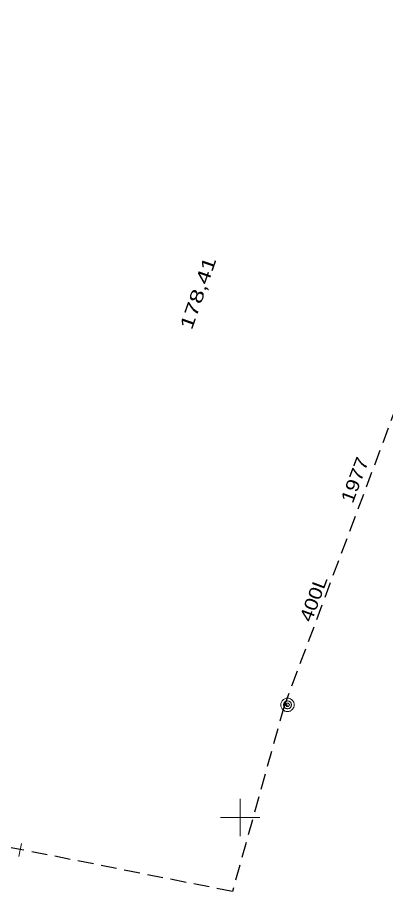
# Model space of a CAD drawing. Extents: x -740851 to -738888, y -1041382 to -1040235.
# Drawn here: x -740667 to -740638.9, y -1040305.7 to -1040239 of the extents above; entities that cross this region are included whole.
import ezdxf

# ---------------------------------------------------------------- set-up
doc = ezdxf.new("R2010")
doc.units = 0
doc.header["$LTSCALE"] = 0.4
doc.linetypes.add('MEDIUM_DASHED', pattern=[4.5, 3, -1.5])
for name, color, linetype, lineweight in [('1', 7, 'Continuous', 13), ('18', 7, 'Continuous', 13), ('8', 7, 'Continuous', 13)]:
    doc.layers.add(name, color=color, linetype=linetype, lineweight=lineweight)

msp = doc.modelspace()

# ---------------------------------------------------------------- linework, layer by layer
at = {"layer": '1'}
for p, q in [((-740650, -1040298.571), (-740650, -1040301.429)), ((-740651.48, -1040300), (-740648.48, -1040300))]:
    msp.add_line(p, q, dxfattribs=at)
at = {"layer": '8'}
for p, q in [((-740646.639, -1040291.414), (-740646.539, -1040291.314)), ((-740646.639, -1040291.314), (-740646.539, -1040291.414)), ((-740646.639, -1040291.314), (-740646.639, -1040291.334)), ((-740646.639, -1040291.314), (-740646.619, -1040291.314)), ((-740646.539, -1040291.314), (-740646.559, -1040291.314)), ((-740646.539, -1040291.314), (-740646.539, -1040291.334)), ((-740646.639, -1040291.414), (-740646.639, -1040291.394)), ((-740646.639, -1040291.414), (-740646.619, -1040291.414)), ((-740646.539, -1040291.414), (-740646.559, -1040291.414)), ((-740646.539, -1040291.414), (-740646.539, -1040291.394)), ((-740666.867, -1040302.98), (-740666.669, -1040301.98))]:
    msp.add_line(p, q, dxfattribs=at)
at = {"layer": '8', "lineweight": 25}
for p, q in [((-740646.59, -1040291.365), (-740646.39, -1040291.44)), ((-740666.76, -1040302.44), (-740667.435, -1040302.329))]:
    msp.add_line(p, q, dxfattribs=at)
at = {"layer": '8', "linetype": 'MEDIUM_DASHED', "lineweight": 25}
for points in [[(-740620.084, -1040238.965), (-740638.07, -1040268.62), (-740646.59, -1040291.365)], [(-740646.59, -1040291.365), (-740646.64, -1040291.5), (-740650.58, -1040305.65), (-740666.76, -1040302.44)]]:
    msp.add_lwpolyline(points, dxfattribs=at)
at = {"layer": '8'}
for points in [[(-740645.875, -1040291.409), (-740645.875, -1040291.364), (-740645.875, -1040291.303), (-740645.89, -1040291.258), (-740645.905, -1040291.197), (-740645.935, -1040291.152), (-740645.965, -1040291.106), (-740645.996, -1040291.076), (-740646.041, -1040291.031), (-740646.072, -1040291), (-740646.117, -1040290.97), (-740646.162, -1040290.94), (-740646.223, -1040290.924), (-740646.268, -1040290.909), (-740646.329, -1040290.909), (-740646.375, -1040290.909), (-740646.435, -1040290.909), (-740646.481, -1040290.909), (-740646.526, -1040290.924), (-740646.587, -1040290.94), (-740646.632, -1040290.97), (-740646.678, -1040291), (-740646.708, -1040291.031), (-740646.753, -1040291.076), (-740646.784, -1040291.106), (-740646.814, -1040291.152), (-740646.844, -1040291.197), (-740646.859, -1040291.258), (-740646.875, -1040291.303), (-740646.875, -1040291.364), (-740646.875, -1040291.409), (-740646.875, -1040291.47), (-740646.875, -1040291.515), (-740646.859, -1040291.561), (-740646.844, -1040291.621), (-740646.814, -1040291.667), (-740646.784, -1040291.712), (-740646.753, -1040291.743), (-740646.708, -1040291.788), (-740646.678, -1040291.818), (-740646.632, -1040291.849), (-740646.587, -1040291.879), (-740646.526, -1040291.894), (-740646.481, -1040291.909), (-740646.435, -1040291.909), (-740646.375, -1040291.909), (-740646.329, -1040291.909), (-740646.268, -1040291.909), (-740646.223, -1040291.894), (-740646.162, -1040291.879), (-740646.117, -1040291.849), (-740646.072, -1040291.818), (-740646.041, -1040291.788), (-740645.996, -1040291.743), (-740645.965, -1040291.712), (-740645.935, -1040291.667), (-740645.905, -1040291.621), (-740645.89, -1040291.561), (-740645.875, -1040291.515), (-740645.875, -1040291.47)], [(-740646.072, -1040291.409), (-740646.072, -1040291.379), (-740646.087, -1040291.349), (-740646.087, -1040291.318), (-740646.102, -1040291.288), (-740646.117, -1040291.258), (-740646.132, -1040291.227), (-740646.147, -1040291.212), (-740646.178, -1040291.182), (-740646.193, -1040291.167), (-740646.223, -1040291.152), (-740646.253, -1040291.137), (-740646.284, -1040291.121), (-740646.314, -1040291.121), (-740646.344, -1040291.106), (-740646.375, -1040291.106), (-740646.405, -1040291.106), (-740646.435, -1040291.121), (-740646.465, -1040291.121), (-740646.496, -1040291.137), (-740646.526, -1040291.152), (-740646.556, -1040291.167), (-740646.572, -1040291.182), (-740646.602, -1040291.212), (-740646.617, -1040291.227), (-740646.632, -1040291.258), (-740646.647, -1040291.288), (-740646.662, -1040291.318), (-740646.662, -1040291.349), (-740646.678, -1040291.379), (-740646.678, -1040291.409), (-740646.678, -1040291.44), (-740646.662, -1040291.47), (-740646.662, -1040291.5), (-740646.647, -1040291.531), (-740646.632, -1040291.561), (-740646.617, -1040291.591), (-740646.602, -1040291.606), (-740646.572, -1040291.637), (-740646.556, -1040291.652), (-740646.526, -1040291.667), (-740646.496, -1040291.682), (-740646.465, -1040291.697), (-740646.435, -1040291.697), (-740646.405, -1040291.712), (-740646.375, -1040291.712), (-740646.344, -1040291.712), (-740646.314, -1040291.697), (-740646.284, -1040291.697), (-740646.253, -1040291.682), (-740646.223, -1040291.667), (-740646.193, -1040291.652), (-740646.178, -1040291.637), (-740646.147, -1040291.606), (-740646.132, -1040291.591), (-740646.117, -1040291.561), (-740646.102, -1040291.531), (-740646.087, -1040291.5), (-740646.087, -1040291.47), (-740646.072, -1040291.44)], [(-740646.539, -1040291.364), (-740646.539, -1040291.359), (-740646.54, -1040291.354), (-740646.541, -1040291.349), (-740646.543, -1040291.344), (-740646.546, -1040291.339), (-740646.549, -1040291.335), (-740646.552, -1040291.331), (-740646.556, -1040291.327), (-740646.56, -1040291.324), (-740646.564, -1040291.321), (-740646.569, -1040291.318), (-740646.574, -1040291.316), (-740646.579, -1040291.315), (-740646.584, -1040291.314), (-740646.589, -1040291.314), (-740646.594, -1040291.314), (-740646.599, -1040291.315), (-740646.604, -1040291.316), (-740646.609, -1040291.318), (-740646.614, -1040291.321), (-740646.618, -1040291.324), (-740646.622, -1040291.327), (-740646.626, -1040291.331), (-740646.629, -1040291.335), (-740646.632, -1040291.339), (-740646.635, -1040291.344), (-740646.637, -1040291.349), (-740646.638, -1040291.354), (-740646.639, -1040291.359), (-740646.639, -1040291.364), (-740646.639, -1040291.369), (-740646.638, -1040291.374), (-740646.637, -1040291.379), (-740646.635, -1040291.384), (-740646.632, -1040291.389), (-740646.629, -1040291.393), (-740646.626, -1040291.397), (-740646.622, -1040291.401), (-740646.618, -1040291.404), (-740646.614, -1040291.407), (-740646.609, -1040291.41), (-740646.604, -1040291.412), (-740646.599, -1040291.413), (-740646.594, -1040291.414), (-740646.589, -1040291.414), (-740646.584, -1040291.414), (-740646.579, -1040291.413), (-740646.574, -1040291.412), (-740646.569, -1040291.41), (-740646.564, -1040291.407), (-740646.56, -1040291.404), (-740646.556, -1040291.401), (-740646.552, -1040291.397), (-740646.549, -1040291.393), (-740646.546, -1040291.389), (-740646.543, -1040291.384), (-740646.541, -1040291.379), (-740646.54, -1040291.374), (-740646.539, -1040291.369)], [(-740646.238, -1040291.409), (-740646.238, -1040291.394), (-740646.253, -1040291.379), (-740646.253, -1040291.364), (-740646.253, -1040291.349), (-740646.268, -1040291.349), (-740646.268, -1040291.334), (-740646.284, -1040291.318), (-740646.299, -1040291.303), (-740646.314, -1040291.303), (-740646.314, -1040291.288), (-740646.329, -1040291.288), (-740646.344, -1040291.288), (-740646.359, -1040291.273), (-740646.375, -1040291.273), (-740646.39, -1040291.273), (-740646.405, -1040291.288), (-740646.42, -1040291.288), (-740646.435, -1040291.288), (-740646.435, -1040291.303), (-740646.45, -1040291.303), (-740646.465, -1040291.318), (-740646.481, -1040291.334), (-740646.496, -1040291.349), (-740646.496, -1040291.364), (-740646.496, -1040291.379), (-740646.511, -1040291.394), (-740646.511, -1040291.409), (-740646.511, -1040291.424), (-740646.496, -1040291.44), (-740646.496, -1040291.455), (-740646.496, -1040291.47), (-740646.481, -1040291.485), (-740646.465, -1040291.5), (-740646.45, -1040291.515), (-740646.435, -1040291.531), (-740646.42, -1040291.531), (-740646.405, -1040291.531), (-740646.39, -1040291.546), (-740646.375, -1040291.546), (-740646.359, -1040291.546), (-740646.344, -1040291.531), (-740646.329, -1040291.531), (-740646.314, -1040291.531), (-740646.299, -1040291.515), (-740646.284, -1040291.5), (-740646.268, -1040291.485), (-740646.268, -1040291.47), (-740646.253, -1040291.47), (-740646.253, -1040291.455), (-740646.253, -1040291.44), (-740646.238, -1040291.424)]]:
    msp.add_lwpolyline(points, close=True, dxfattribs=at)

# ---------------------------------------------------------------- texts
at = {"layer": '18', "width": 1.4}
msp.add_text('178,41', height=1, rotation=70.718, dxfattribs=at).set_placement((-740653.676, -1040262.858))
at = {"layer": '8', "width": 1.2}
for s, rotation, p in [('1977', 69.466, (-740641.407, -1040276.098)), ('400L', 69.465, (-740644.558, -1040285.162))]:
    msp.add_text(s, height=1, rotation=rotation, dxfattribs=at).set_placement(p)

doc.saveas('drawing.dxf')
